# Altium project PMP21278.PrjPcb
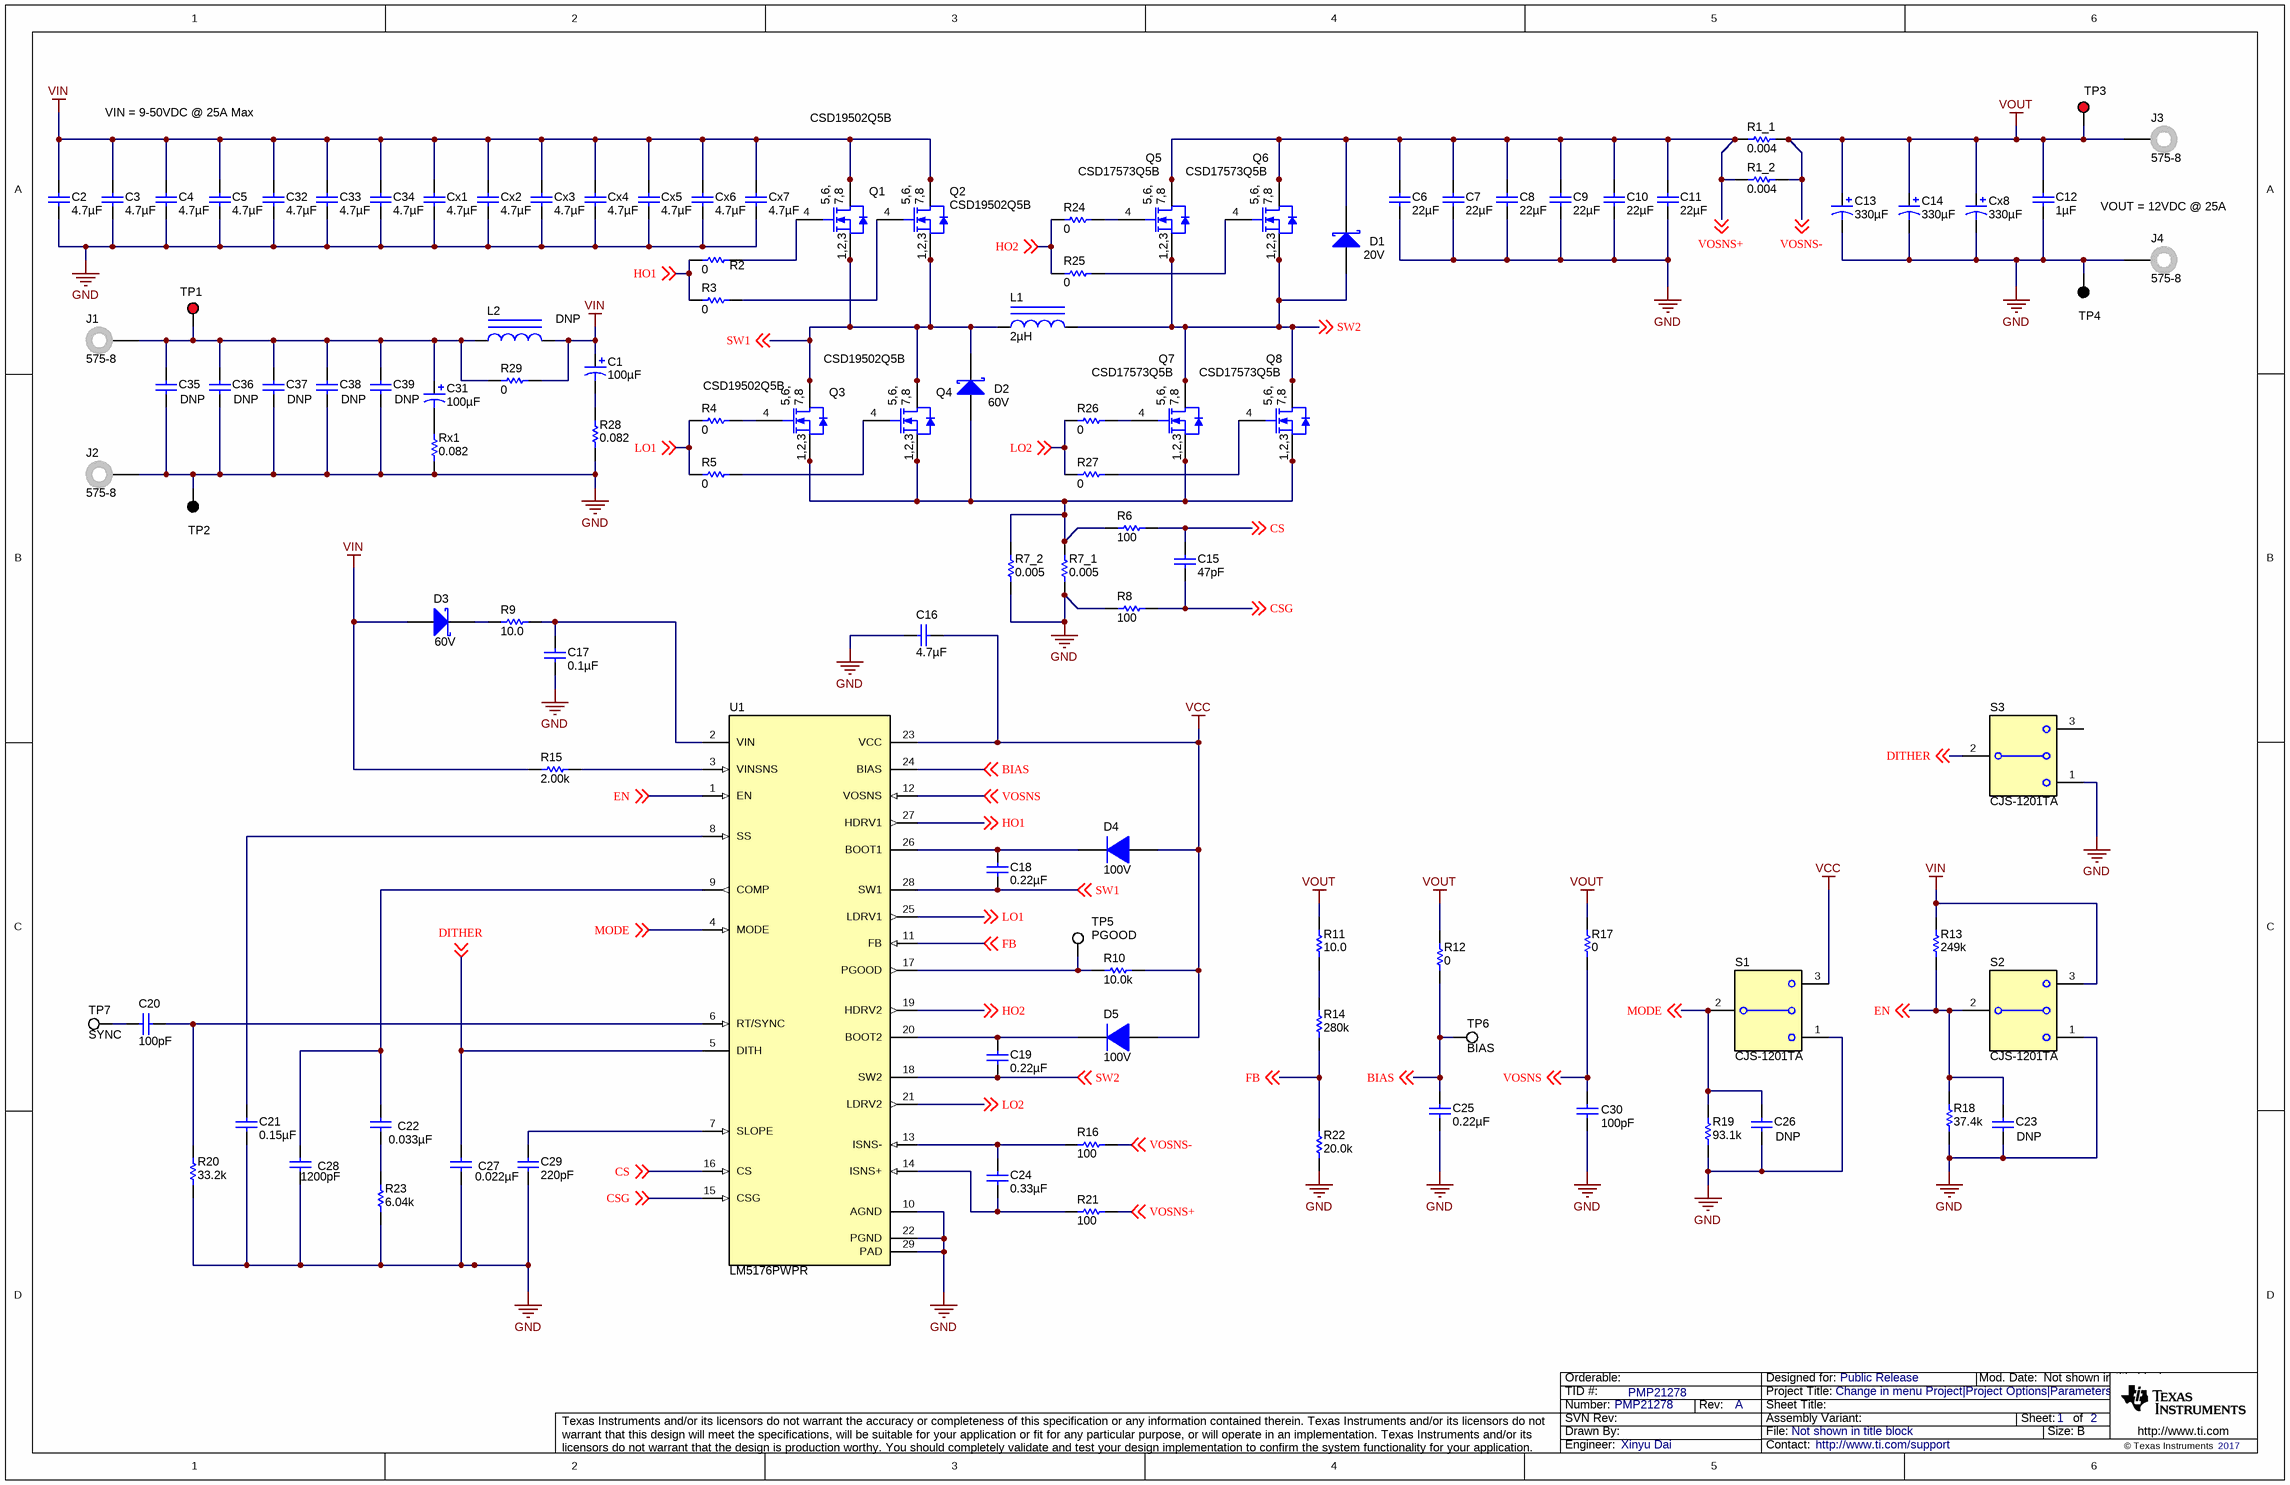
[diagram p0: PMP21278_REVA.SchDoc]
TID: PMP21278; TechSupport: http://www.ti.com/support; SCH_Rev: A; PRJ_Title: Change in menu Project|Project Options|Parameters; PRJ_Number: PMP21278; PRJ_Engineer: Xinyu Dai; PRJ_Customer: Public Release; PCB_Rev: A; PCB_Layout: Xinyu Dai; CopyrightYear: 2017
2 sheets, 125 parts. Net scope: global (net labels, ports and power ports of the same name join across sheets).
Board file: SV601348A.PcbDoc
Sheets:
  PMP21278_REVA.SchDoc
  SV601348_REVA_Hardware.SchDoc

## Sheet PMP21278_REVA.SchDoc
size 431 x 279 mm; Date: Not shown in title block; ApprovedBy: Not shown in title block; CheckedBy: Not shown in title block; Author: Not shown in title block; CompanyName: Not shown in title block; Engineer: Not shown in title block; Organization: Not shown in title block; Address1: Not shown in title block; Address2: Not shown in title block; Address3: Not shown in title block; Address4: Not shown in title block; DocumentNumber: 1; Revision: Use project parameter SCH_Rev; SheetNumber: 1; SheetTotal: 2; PageSetup: Record=PageOptions¦CenterHorizontal=True¦CenterVertical=True¦PrintScale=1.00¦XCorrection=1.00¦YCorrection=1.00¦PrintKind=0¦BorderSize=5000000¦LeftOffset=0¦BottomOffset=0¦Orientation=2¦PaperLength=1000¦PaperWidth=1000¦Scale=100¦PaperSource=15¦PrintQuality=600¦MediaType=1¦DitherType=10¦PaperKind=Letter¦PrintScaleMode=1

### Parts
C1  ValueDisplayed: 100µF  [CR_1000x1270]  (hidden comment: PCR1J101MCL1GS)
C2  ValueDisplayed: 4.7µF  [1210_270]  (hidden comment: GRM32ER71K475KE14L)
C3  ValueDisplayed: 4.7µF  [1210_270]  (hidden comment: GRM32ER71K475KE14L)
C4  ValueDisplayed: 4.7µF  [1210_270]  (hidden comment: GRM32ER71K475KE14L)
C5  ValueDisplayed: 4.7µF  [1210_270]  (hidden comment: GRM32ER71K475KE14L)
C6  ValueDisplayed: 22µF  [1210_270]  (hidden comment: GRM32ER71E226KE15L)
C7  ValueDisplayed: 22µF  [1210_270]  (hidden comment: GRM32ER71E226KE15L)
C8  ValueDisplayed: 22µF  [1210_270]  (hidden comment: GRM32ER71E226KE15L)
C9  ValueDisplayed: 22µF  [1210_270]  (hidden comment: GRM32ER71E226KE15L)
C10  ValueDisplayed: 22µF  [1210_270]  (hidden comment: GRM32ER71E226KE15L)
C11  ValueDisplayed: 22µF  [1210_270]  (hidden comment: GRM32ER71E226KE15L)
C12  ValueDisplayed: 1µF  [0805_HV]  (hidden comment: GRM219R71E105KA88D)
C13  ValueDisplayed: 330µF  [SM_RADIAL_10AMM]  (hidden comment: 16SVP330M)
C14  ValueDisplayed: 330µF  [SM_RADIAL_10AMM]  (hidden comment: 16SVP330M)
C15  ValueDisplayed: 47pF  [0603L]  (hidden comment: GRM1885C1H470JA01D)
C16  ValueDisplayed: 4.7µF  [0805_HV]  (hidden comment: GRM21BR71C475KA73L)
C17  ValueDisplayed: 0.1µF  [0603L]  (hidden comment: GRM188R72A104KA35D)
C18  ValueDisplayed: 0.22µF  [0603L]  (hidden comment: GRM188R71E224KA88D)
C19  ValueDisplayed: 0.22µF  [0603L]  (hidden comment: GRM188R71E224KA88D)
C20  ValueDisplayed: 100pF  [0603L]  (hidden comment: GRM1885C2A101JA01D)
C21  ValueDisplayed: 0.15µF  [0603]  (hidden comment: GRM188R71E154KA01D)
C22  ValueDisplayed: 0.033µF  [0603L]  (hidden comment: GRM188R71H333KA61D)
C23  DNP  [0603L]
C24  ValueDisplayed: 0.33µF  [0603L]  (hidden comment: GRM188R71C334KA01D)
C25  ValueDisplayed: 0.22µF  [0603]  (hidden comment: GRM188R71E224KA88D)
C26  DNP  [0603L]
C27  ValueDisplayed: 0.022µF  [0603L]  (hidden comment: C0603C223K5RACTU)
C28  ValueDisplayed: 1200pF  [0603]  (hidden comment: GRM188R71E122KA01D)
C29  ValueDisplayed: 220pF  [0603]  (hidden comment: GRM1885C1H221JA01D)
C30  ValueDisplayed: 100pF  [0603L]  (hidden comment: GRM1885C2A101JA01D)
C31  ValueDisplayed: 100µF  [CR_1000x1270]  (hidden comment: PCR1J101MCL1GS)
C32  ValueDisplayed: 4.7µF  [1210_270]  (hidden comment: GRM32ER71K475KE14L)
C33  ValueDisplayed: 4.7µF  [1210_270]  (hidden comment: GRM32ER71K475KE14L)
C34  ValueDisplayed: 4.7µF  [1210_270]  (hidden comment: GRM32ER71K475KE14L)
C35  DNP  [1210_270]
C36  DNP  [1210_270]
C37  DNP  [1210_270]
C38  DNP  [1210_270]
C39  DNP  [1210_270]
Cx1  ValueDisplayed: 4.7µF  [1210_270]  (hidden comment: GRM32ER71K475KE14L)
Cx2  ValueDisplayed: 4.7µF  [1210_270]  (hidden comment: GRM32ER71K475KE14L)
Cx3  ValueDisplayed: 4.7µF  [1210_270]  (hidden comment: GRM32ER71K475KE14L)
Cx4  ValueDisplayed: 4.7µF  [1210_270]  (hidden comment: GRM32ER71K475KE14L)
Cx5  ValueDisplayed: 4.7µF  [1210_270]  (hidden comment: GRM32ER71K475KE14L)
Cx6  ValueDisplayed: 4.7µF  [1210_270]  (hidden comment: GRM32ER71K475KE14L)
Cx7  ValueDisplayed: 4.7µF  [1210_270]  (hidden comment: GRM32ER71K475KE14L)
Cx8  ValueDisplayed: 330µF  [SM_RADIAL_10AMM]  (hidden comment: 16SVP330M)
D1  20V  [SMA]
D2  60V  [SMA]
D3  60V  [SOD-323F]
D4  100V  [sod-323]
D5  100V  [sod-323]
J1  575-8  [Keystone575-8]
J2  575-8  [Keystone575-8]
J3  575-8  [Keystone575-8]
J4  575-8  [Keystone575-8]
L1  ValueDisplayed: 2µH  [XAL1580]  (hidden comment: XAL1580-202MEB)
L2  DNP  [XAL1010]
Q1  CSD19502Q5B  [DNK0008A]
Q2  CSD19502Q5B  [DNK0008A]
Q3  CSD19502Q5B  [DNK0008A]
Q4  CSD19502Q5B  [DNK0008A]
Q5  CSD17573Q5B  [DNK0008A]
Q6  CSD17573Q5B  [DNK0008A]
Q7  CSD17573Q5B  [DNK0008A]
Q8  CSD17573Q5B  [DNK0008A]
R1_1  ValueDisplayed: 0.004  [2512_WIDE]  (hidden comment: KRL6432E-M-R004-F-T1)
R1_2  ValueDisplayed: 0.004  [2512_WIDE]  (hidden comment: KRL6432E-M-R004-F-T1)
R2  value 0  [0603L]  (hidden comment: RC0603JR-070RL)
R3  value 0  [0603L]  (hidden comment: RC0603JR-070RL)
R4  value 0  [0603L]  (hidden comment: RC0603JR-070RL)
R5  value 0  [0603L]  (hidden comment: RC0603JR-070RL)
R6  value 100  [0603_HV]  (hidden comment: RC0603FR-07100RL)
R7_1  ValueDisplayed: 0.005  [2512_WIDE]  (hidden comment: FCSL64R005FER)
R7_2  ValueDisplayed: 0.005  [2512_WIDE]  (hidden comment: FCSL64R005FER)
R8  value 100  [0603_HV]  (hidden comment: RC0603FR-07100RL)
R9  value 10.0  [0603L]  (hidden comment: RC0603FR-0710RL)
R10  value 10.0k  [0603L]  (hidden comment: RC0603FR-0710KL)
R11  value 10.0  [0603L]  (hidden comment: RC0603FR-0710RL)
R12  value 0  [0603L]  (hidden comment: RC0603JR-070RL)
R13  value 249k  [0603L]  (hidden comment: RC0603FR-07249KL)
R14  value 280k  [0603L]  (hidden comment: RC0603FR-07280KL)
R15  ValueDisplayed: 2.00k  [0603]  (hidden comment: CRCW06032K00FKEA)
R16  100  [0603L]
R17  value 0  [0603L]  (hidden comment: RC0603JR-070RL)
R18  ValueDisplayed: 37.4k  [0603]  (hidden comment: CRCW060337K4FKEA)
R19  ValueDisplayed: 93.1k  [0603L]  (hidden comment: RC0603FR-0793K1L)
R20  ValueDisplayed: 33.2k  [0603L]  (hidden comment: CRCW060333K2FKEA)
R21  100  [0603L]
R22  value 20.0k  [0603L]  (hidden comment: RC0603FR-0720KL)
R23  ValueDisplayed: 6.04k  [0603]  (hidden comment: CRCW06036K04FKEA)
R24  value 0  [0603L]  (hidden comment: RC0603JR-070RL)
R25  value 0  [0603L]  (hidden comment: RC0603JR-070RL)
R26  value 0  [0603L]  (hidden comment: RC0603JR-070RL)
R27  value 0  [0603L]  (hidden comment: RC0603JR-070RL)
R28  ValueDisplayed: 0.082  [2512]  (hidden comment: RLP73N3AR082FTDF)
R29  ValueDisplayed: 0  [2512_WIDE_VISHAY]  (hidden comment: RCL12250000Z0EG)
Rx1  ValueDisplayed: 0.082  [2512]  (hidden comment: RLP73N3AR082FTDF)
S1  CJS-1201TA  [SW_CJS_1201A]
S2  CJS-1201TA  [SW_CJS_1201A]
S3  CJS-1201TA  [SW_CJS_1201A]
TP1  5005  [Keystone5005]  (value not drawn)
TP2  5006  [Keystone5006]  (value not drawn)
TP3  5005  [Keystone5005]  (value not drawn)
TP4  5006  [Keystone5006]  (value not drawn)
TP5  PGOOD  [Keystone5007]
TP6  BIAS  [Keystone5007]
TP7  SYNC  [Keystone5007]
U1  LM5176PWPR  [PWP0028C_N]

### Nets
GND: C2.2 C3.2 C4.2 C5.2 C6.2 C7.2 C8.2 C9.2 C10.2 C11.2 C12.2 C13.2(-) C14.2(-) C16.1 C17.2 C21.2 C23.2 C25.2 C26.2 C27.2 C28.2 C29.2 C30.2 C32.2 C33.2 C34.2 C35.2 C36.2 C37.2 C38.2 C39.2 Cx1.2 Cx2.2 Cx3.2 Cx4.2 Cx5.2 Cx6.2 Cx7.2 Cx8.2(-) J2.1 J4.1 R7_1.1 R7_2.1 R8.2 R18.1 R19.1 R20.1 R22.1 R23.1 R28.1 Rx1.1 S1.1 S2.1 S3.1 TP2.1 TP4.1 U1.10(AGND) U1.22(PGND) U1.29(PAD)
VCC: C16.2 D4.2(A) D5.2(A) R10.2 S1.3 U1.23(VCC)
VIN: C1.1(+) C2.1 C3.1 C4.1 C5.1 C32.1 C33.1 C34.1 Cx1.1 Cx2.1 Cx3.1 Cx4.1 Cx5.1 Cx6.1 Cx7.1 D3.2(A) L2.2 Q1.5(D) Q1.6(D) Q1.7(D) Q1.8(D) Q1.9(D) Q2.5(D) Q2.6(D) Q2.7(D) Q2.8(D) Q2.9(D) R13.2 R15.2 R29.2 S2.3
VOUT: C12.1 C13.1(+) C14.1(+) Cx8.1(+) J3.1 R1_1.2 R1_2.2 R11.1 R12.1 R16.2 R17.1 TP3.1 ; off-sheet VOSNS-  [also labelled VOSNS-]
BIAS: C25.1 R12.2 TP6.1 U1.24(BIAS) ; off-sheet BIAS
CS: C15.1 R6.1 U1.16(CS) ; off-sheet CS
CSG: C15.2 R8.1 U1.15(CSG) ; off-sheet CSG
DITHER: C27.1 S3.2(COM) U1.5(DITH) ; off-sheet DITHER
EN: C23.1 R13.1 R18.2 S2.2(COM) U1.1(EN) ; off-sheet EN
FB: R14.1 R22.2 U1.11(FB) ; off-sheet FB
HO1: R2.2 R3.2 U1.27(HDRV1) ; off-sheet HO1
HO2: R24.2 R25.2 U1.19(HDRV2) ; off-sheet HO2
LO1: R4.2 R5.2 U1.25(LDRV1) ; off-sheet LO1
LO2: R26.2 R27.2 U1.21(LDRV2) ; off-sheet LO2
MODE: C26.1 R19.2 S1.2(COM) U1.4(MODE) ; off-sheet MODE
SW1: C18.1 D2.1(K) L1.1 Q1.1(S) Q1.2(S) Q1.3(S) Q2.1(S) Q2.2(S) Q2.3(S) Q3.5(D) Q3.6(D) Q3.7(D) Q3.8(D) Q3.9(D) Q4.5(D) Q4.6(D) Q4.7(D) Q4.8(D) Q4.9(D) U1.28(SW1) ; off-sheet SW1
SW2: C19.2 D1.2(A) L1.2 Q5.1(S) Q5.2(S) Q5.3(S) Q6.1(S) Q6.2(S) Q6.3(S) Q7.5(D) Q7.6(D) Q7.7(D) Q7.8(D) Q7.9(D) Q8.5(D) Q8.6(D) Q8.7(D) Q8.8(D) Q8.9(D) U1.18(SW2) ; off-sheet SW2
VOSNS: C30.1 R17.2 U1.12(VOSNS) ; off-sheet VOSNS
VOSNS+: C6.1 C7.1 C8.1 C9.1 C10.1 C11.1 D1.1(K) Q5.5(D) Q5.6(D) Q5.7(D) Q5.8(D) Q5.9(D) Q6.5(D) Q6.6(D) Q6.7(D) Q6.8(D) Q6.9(D) R1_1.1 R1_2.1 R21.2 ; off-sheet VOSNS+
NetC1_2: C1.2(-) R28.2
NetC17_1: C17.1 R9.1 U1.2(VIN)
NetC18_2: C18.2 D4.1(K) U1.26(BOOT1)
NetC19_1: C19.1 D5.1(K) U1.20(BOOT2)
NetC20_1: C20.1 TP7.1
NetC20_2: C20.2 R20.2 U1.6(RT/SYNC)
NetC21_1: C21.1 U1.8(SS)
NetC22_1: C22.1 C28.1 U1.9(COMP)
NetC22_2: C22.2 R23.2
NetC24_1: C24.1 R16.1 U1.13(ISNS-)
NetC24_2: C24.2 R21.1 U1.14(ISNS+)
NetC29_1: C29.1 U1.7(SLOPE)
NetC31_1: C31.1(+) C35.1 C36.1 C37.1 C38.1 C39.1 J1.1 L2.1 R29.1 TP1.1
NetC31_2: C31.2(-) Rx1.2
NetD2_2: D2.2(A) Q3.1(S) Q3.2(S) Q3.3(S) Q4.1(S) Q4.2(S) Q4.3(S) Q7.1(S) Q7.2(S) Q7.3(S) Q8.1(S) Q8.2(S) Q8.3(S) R6.2 R7_1.2 R7_2.2
NetD3_1: D3.1(K) R9.2
NetQ1_4: Q1.4(G) R2.1
NetQ2_4: Q2.4(G) R3.1
NetQ3_4: Q3.4(G) R4.1
NetQ4_4: Q4.4(G) R5.1
NetQ5_4: Q5.4(G) R24.1
NetQ6_4: Q6.4(G) R25.1
NetQ7_4: Q7.4(G) R26.1
NetQ8_4: Q8.4(G) R27.1
NetR10_1: R10.1 TP5.1 U1.17(PGOOD)
NetR11_2: R11.2 R14.2
NetR15_1: R15.1 U1.3(VINSNS)

Not connected (* = marked no-connect by the designer): S3 3

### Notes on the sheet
- VIN = 9-50VDC @ 25A Max
- VOUT = 12VDC @ 25A

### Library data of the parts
C1 C31 = PCR1J101MCL1GS: CAP, Aluminum Polymer, 100 µF, 63 V, +/- 20%, 0.024 ohm, SMD, 2-Leads, Dia 10.5mm, Pin Spacing 8mm SMD; Manufacturer: Nichicon; Polarized: Y; CompType: Capacitor; Value: 100uF; U/M: EA; Cap_F: 0.0001; Tolerance_%: 20; VDC_V: 63; Value2: 63V; ESR_ohm: 0.024; IRMS_A: 3; TaMin_C: -55; TaMax_C: 125; Cap_Case: 10x12.7mm; AEC Category: Q200; AEC Qualified: N
C2-C5 C32-C34 Cx1-Cx7 = GRM32ER71K475KE14L: CAP, CERM, 4.7 µF, 80 V, +/- 10%, X7R, 1210; Manufacturer: MuRata; CompType: Capacitor; Value: 4.7uF; U/M: EA; Tolerance_%: 10; VDC_V: 80; Polarized: N; Cap_F: 0.0000047; Value1: Unknown; Value2: 80V; TaMin_C: -55; TaMax_C: 125; Cap_Case: 1210; SizeArea_mm2: 8; SizeAreaWB_mm2: 14.7; SizeX_mm: 3.2; SizeY_mm: 2.5; SizeZ_mm: 2.7; AEC Category: Q200
C6-C11 = GRM32ER71E226KE15L: CAP, CERM, 22 µF, 25 V, +/- 10%, X7R, 1210; Manufacturer: MuRata; CompType: Capacitor; Value: 22uF; U/M: EA; Tolerance_%: 10; VDC_V: 25; Polarized: N; Cap_F: 0.000022; Value1: Unknown; Value2: 25V; TaMin_C: -55; TaMax_C: 125; Cap_Case: 1210; SizeArea_mm2: 8; SizeAreaWB_mm2: 14.7; SizeX_mm: 3.2; SizeY_mm: 2.5; SizeZ_mm: 2.7; AEC Category: Q200
C12 = GRM219R71E105KA88D: CAP, CERM, 1 µF, 25 V, +/- 10%, X7R, 0805; Manufacturer: MuRata; Polarized: N; CompType: Capacitor; Value: 1uF; U/M: EA; Cap_F: 0.000001; Tolerance_%: 10; Value1: Unknown; VDC_V: 25; Value2: 25V; TaMin_C: -55; TaMax_C: 125; Cap_Case: 0805
C13 C14 Cx8 = 16SVP330M: CAP, OS-CON, 330 µF, 16 V, +/- 20%, 0.016 ohm, 10x10.3 SMD; Manufacturer: Sanyo; CompType: Capacitor; Value: 330uF; U/M: EA; Tolerance_%: 20; VDC_V: 16; ESR_ohm: 0.016; Polarized: Y; Cap_F: 0.00033; Value2: 16V; IRMS_A: 4.72; TaMin_C: -55; TaMax_C: 105; Cap_Case: 10.3x10.3x12.6
C15 C23 C26 = GRM1885C1H470JA01D: CAP, CERM, 47pF, 50V, +/-5%, C0G/NP0, 0603; Manufacturer: MuRata; Polarized: N; CompType: Capacitor; U/M: EA; Cap_F: 0.000000000047; Tolerance_%: 5; Value1: Unknown; VDC_V: 50; TaMin_C: -55; TaMax_C: 125; Cap_Case: 0603
C16 = GRM21BR71C475KA73L: CAP, CERM, 4.7 µF, 16 V, +/- 10%, X7R, 0805; Manufacturer: MuRata; Polarized: N; CompType: Capacitor; Value: 4.7uF; U/M: EA; Cap_F: 0.0000047; Tolerance_%: 10; ESR_ohm: 0.006; Value1: 0.006 ohm; VDC_V: 16; Value2: 16V; TaMin_C: -55; TaMax_C: 125; Cap_Case: 0805
C17 = GRM188R72A104KA35D: CAP, CERM, 0.1uF, 100V, +/-10%, X7R, 0603; Manufacturer: MuRata; Polarized: N; CompType: Capacitor; U/M: EA; Cap_F: 0.0000001; Tolerance_%: 10; Value1: Unknown; VDC_V: 100; TaMin_C: -55; TaMax_C: 125; Cap_Case: 0603
C18 C19 = GRM188R71E224KA88D: CAP, CERM, 0.22 µF, 25 V, +/- 10%, X7R, 0603; Manufacturer: MuRata; Polarized: N; CompType: Capacitor; Value: 0.22uF; U/M: EA; Cap_F: 0.00000022; Tolerance_%: 10; Value1: Unknown; VDC_V: 25; Value2: 25V; TaMin_C: -55; TaMax_C: 125; Cap_Case: 0603
C20 C30 = GRM1885C2A101JA01D: CAP, CERM, 100pF, 100V, +/-5%, C0G/NP0, 0603; Manufacturer: MuRata; Polarized: N; CompType: Capacitor; U/M: EA; Cap_F: 0.0000000001; Tolerance_%: 5; Value1: Unknown; VDC_V: 100; TaMin_C: -55; TaMax_C: 125; Cap_Case: 0603
C21 = GRM188R71E154KA01D: CAP, CERM, 0.15 µF, 25 V,+/- 10%, X7R, 0603; Manufacturer: MuRata; Polarized: N; CompType: Capacitor; Value: 0.15uF; U/M: EA; Cap_F: 0.00000015; Tolerance_%: 10; Value1: Unknown; VDC_V: 25; Value2: 25V; TaMin_C: -55; TaMax_C: 125; SizeArea_mm2: 1.28; SizeAreaWB_mm2: 4.68; SizeX_mm: 1.6; SizeY_mm: 0.8; SizeZ_mm: 1; AEC Category: Q200; Green_Lifecycle: Active; Green_REACh: Passed
C22 = GRM188R71H333KA61D: CAP, CERM, 0.033 µF, 50 V, +/- 10%, X7R, 0603; Manufacturer: MuRata; Polarized: N; CompType: Capacitor; Value: 0.033uF; U/M: EA; Cap_F: 0.000000033; Tolerance_%: 10; Value1: Unknown; VDC_V: 50; Value2: 50V; TaMin_C: -55; TaMax_C: 125; Cap_Case: 0603; SizeArea_mm2: 1.28; SizeAreaWB_mm2: 4.68; SizeX_mm: 1.6; SizeY_mm: 0.8; SizeZ_mm: 1; AEC Category: Q200
C24 = GRM188R71C334KA01D: CAP, CERM, 0.33 µF, 16 V, +/- 10%, X7R, 0603; Manufacturer: MuRata; Polarized: N; CompType: Capacitor; Value: 0.33uF; U/M: EA; Cap_F: 0.00000033; Tolerance_%: 10; Value1: Unknown; VDC_V: 16; Value2: 16V; TaMin_C: -55; TaMax_C: 125; Cap_Case: 0603
C25 = GRM188R71E224KA88D: CAP, CERM, 0.22 µF, 25 V, +/- 10%, X7R, 0603; Manufacturer: MuRata; Polarized: N; CompType: Capacitor; Value: 0.22uF; U/M: EA; Cap_F: 0.00000022; Tolerance_%: 10; Value1: Unknown; VDC_V: 25; Value2: 25V; TaMin_C: -55; TaMax_C: 125
C27 = C0603C223K5RACTU: CAP, CERM, 0.022uF, 50V, +/-10%, X7R, 0603; Manufacturer: Kemet; Polarized: N; CompType: Capacitor; U/M: EA; Cap_F: 0.000000022; Tolerance_%: 10; Value1: Unknown; VDC_V: 50; TaMin_C: -55; TaMax_C: 125; Cap_Case: 0603
C28 = GRM188R71E122KA01D: CAP, CERM, 1200 pF, 25 V,+/- 10%, X7R, 0603; Manufacturer: MuRata; Polarized: N; CompType: Capacitor; Value: 1200pF; U/M: EA; Cap_F: 0.0000000012; Tolerance_%: 10; Value1: Unknown; VDC_V: 25; Value2: 25V; TaMin_C: -55; TaMax_C: 125; SizeArea_mm2: 1.28; SizeAreaWB_mm2: 4.68; SizeX_mm: 1.6; SizeY_mm: 0.8; SizeZ_mm: 1; AEC Category: Q200
C29 = GRM1885C1H221JA01D: CAP, CERM, 220 pF, 50 V,+/- 5%, C0G/NP0, 0603; Manufacturer: MuRata; Polarized: N; CompType: Capacitor; Value: 220pF; U/M: EA; Cap_F: 0.00000000022; Tolerance_%: 5; Value1: Unknown; VDC_V: 50; Value2: 50V; TaMin_C: -55; TaMax_C: 125; SizeArea_mm2: 1.28; SizeAreaWB_mm2: 4.68; SizeX_mm: 1.6; SizeY_mm: 0.8; SizeZ_mm: 1; AEC Category: Q200; Green_Lifecycle: Active; Green_REACh: Passed
C35-C39 = GRM32ER71K475KE14L: CAP, CERM, 4.7 µF, 80 V, +/- 10%, X7R, 1210; Manufacturer: MuRata; CompType: Capacitor; Value: 4.7uF; U/M: EA; Tolerance_%: 10; VDC_V: 80; Polarized: N; ValueDisplayed: 4.7µF; Cap_F: 0.0000047; Value1: Unknown; Value2: 80V; TaMin_C: -55; TaMax_C: 125; Cap_Case: 1210; SizeArea_mm2: 8; SizeAreaWB_mm2: 14.7; SizeX_mm: 3.2; SizeY_mm: 2.5; SizeZ_mm: 2.7; AEC Category: Q200
D1 = RSX501L-20TE25: Diode, Schottky, 20 V, 5 A, SMA; Manufacturer: Rohm; U/M: EA; Vf_V: 0.39; Value1: 5A; Value2: 0.39V; Io_A: 5; Vr_V: 20; TJmax_C: 125
D2 = RB050L-60TE25: Diode, Schottky, 60 V, 3 A, SMA; Manufacturer: Rohm; U/M: EA; Vf_V: 0.56; Value1: 3A; Value2: 0.56V; Io_A: 3; Vr_V: 60; TJmax_C: 150
D3 = PMEG6010CEJ,115: Diode, Schottky, 60 V, 1 A, SOD-323F; Manufacturer: NXP Semiconductor; U/M: EA; Vf_V: 0.66; Value1: 1A; Value2: 0.66V; Io_A: 1; Vr_V: 60; TJmax_C: 150
D4 D5 = BAS316,115: Diode, Ultrafast, 100V, 0.25A, SOD-323; Manufacturer: NXP Semiconductor; U/M: EA; Vr_V: 100; Io_A: 0.25; Vf_V: 1.4; Value2: 1.4V; TJmax_C: 150
J1-J4 = 575-8: Standard Banana Jack, Uninsulated, 8.9mm; Manufacturer: Keystone; CompType: Connector
L1 = XAL1580-202MEB: Inductor, Shielded, Composite, 2 µH, 39.9 A, 0.001909 ohm, SMD; Manufacturer: Coilcraft; Value: 2uH; Ind_H: 2.0E-6; Imax_A: 39.9; Irms: 39.9A @ 40C rise; Isat: 51A @ 0.7% inductance drop; Value2: 39.9A; SizeAreaWB_mm2: 313.04; SizeArea_mm2: 246.24; SizeX_mm: 15.2; SizeY_mm: 16.2; SizeZ_mm: 8; AEC Category: Q200; Green_Lifecycle: Not Set; Green_REACh: Incomplete
L2 = XAL1010-222MEB: Inductor, Shielded, Composite, 2.2 µH, 32 A, 0.00255 ohm, SMD; Manufacturer: Coilcraft; Value: 2.2uH; ValueDisplayed: 2.2µH; Ind_H: 2.2E-6; Imax_A: 32; Irms: 32A @ 40C rise; Isat: 34A @ 30% inductance drop; Value2: 32A; SizeAreaWB_mm2: 159.6; SizeArea_mm2: 113; SizeX_mm: 11.3; SizeY_mm: 10; AEC Category: Q200
Q1-Q4 = CMP-0000915-1: MOSFET, N-CH, 80 V, 100 A, DNK0008A (VSON-CLIP-8); Alternate Manufacturer: None; Manufacturer: Texas Instruments; SizeZ_mm: 1; ChType: N; Value2: 48 nC; VdsMax_V: 80V; SizeX_mm: 6; SizeY_mm: 5; Vgs_V: 20V; Value: 80V; SizeArea_mm2: 30; AEC Category: Q101; IdsMax_A: 100A; SizeAreaWB_mm2: 56; U/M: EA; QgTyp_nC: 48
Q5-Q8 = CSD17573Q5B: MOSFET, N-CH, 30 V, 100 A, DNK0008A (VSON-CLIP-8); Manufacturer: Texas Instruments; Alternate Manufacturer: None; U/M: EA; ChType: N; Value: 30V; VdsMax_V: 30; Value1: 0.00145 ohm; Rdson45_ohm: 0.00145; Value2: 49 nC; QgTyp_nC: 49; Vgs_V: 20; IdsMax_A: 100; SizeAreaWB_mm2: 56; SizeX_mm: 6; SizeY_mm: 5; SizeZ_mm: 1; AEC Category: Q101
R1_1 R1_2 = KRL6432E-M-R004-F-T1: RES, 0.004, 1%, 3 W, 2512 WIDE; Manufacturer: Susumu Co Ltd; CompType: Resistor; U/M: EA; Value: 0.004; Power_W: 3; Tolerance_%: 1; TempCo: 50 ppm/C; Value_Code: 4L000; Value2: 3W; SizeArea_mm2: 20.16; SizeAreaWB_mm2: 43.16; SizeX_mm: 3.2; SizeY_mm: 6.3; SizeZ_mm: 0.7; AEC Category: Q200
R2-R5 R12 R17 R24-R27 = RC0603JR-070RL: RES, 0 ohm, 5%, 0.1W, 0603; Manufacturer: Yageo America; CompType: Resistor; Value_Code: 0000; Tolerance_%: 5; Power_W: 0.1; VDC_V: 50; TempCo: 200 ppm/C; EIA_Code: E24; U/M: EA
R6 R8 R16 R21 = RC0603FR-07100RL: RES, 100 ohm, 1%, 0.1W, 0603; Manufacturer: Yageo America; CompType: Resistor; Value_Code: 100R; Tolerance_%: 1; Power_W: 0.1; VDC_V: 150; TempCo: 200 ppm/C; EIA_Code: E96; U/M: EA
R7_1 = FCSL64R005FER: RES, 0.005, 1%, 2 W, 2512 WIDE; Manufacturer: Ohmite; CompType: Resistor; Value: 0.005; Tolerance_%: 1; Power_W: 2; TempCo: 75 ppm/C; U/M: EA; Value_Code: 5L000; Value2: 2W; EIA_Code: E96; SizeArea_mm2: 20.16; SizeAreaWB_mm2: 43.16; SizeX_mm: 3.2; SizeY_mm: 6.3; SizeZ_mm: 0.7; AEC Category: Q200
R7_2 = FCSL64R005FER: RES, 0.005, 1%, 2 W, 2512 WIDE; Manufacturer: Ohmite; CompType: Resistor; Value: 0.005; Value_Code: 5L000; Tolerance_%: 1; Power_W: 2; Value2: 2W; TempCo: 75 ppm/C; SizeArea_mm2: 20.16; SizeAreaWB_mm2: 43.16; SizeX_mm: 3.2; SizeY_mm: 6.3; SizeZ_mm: 0.7; EIA_Code: E96; U/M: EA; AEC Category: Q200
R9 R11 = RC0603FR-0710RL: RES, 10.0 ohm, 1%, 0.1W, 0603; Manufacturer: Yageo America; CompType: Resistor; Res_ohm: 10; Value_Code: 10R0; Tolerance_%: 1; Power_W: 0.1; VDC_V: 150; TempCo: 200 ppm/C; EIA_Code: E96; U/M: EA
R10 = RC0603FR-0710KL: RES, 10.0k ohm, 1%, 0.1W, 0603; Manufacturer: Yageo America; CompType: Resistor; Res_ohm: 10000; Value_Code: 10k0; Tolerance_%: 1; Power_W: 0.1; VDC_V: 150; TempCo: 200 ppm/C; EIA_Code: E96; U/M: EA
R13 = RC0603FR-07249KL: RES, 249k ohm, 1%, 0.1W, 0603; Manufacturer: Yageo America; CompType: Resistor; Res_ohm: 249000; Tolerance_%: 1; Power_W: 0.1; VDC_V: 150; TempCo: 200 ppm/C; EIA_Code: E96; U/M: EA
R14 = RC0603FR-07280KL: RES, 280k ohm, 1%, 0.1W, 0603; Manufacturer: Yageo America; CompType: Resistor; Res_ohm: 280000; Tolerance_%: 1; Power_W: 0.1; VDC_V: 150; TempCo: 200 ppm/C; EIA_Code: E96; U/M: EA
R15 = CRCW06032K00FKEA: RES, 2.00 k, 1%, 0.1 W, 0603; Manufacturer: Vishay-Dale; CompType: Resistor; Value: 2.00k; Res_ohm: 2000; Value_Code: 2k00; Tolerance_%: 1; Power_W: 0.1; Value2: 0.1W; VDC_V: 75; TempCo: 100 ppm/C; EIA_Code: E96; U/M: EA; SizeArea_mm2: 1.28; SizeX_mm: 1.6; SizeY_mm: 0.8; AEC Category: Q200
R18 = CRCW060337K4FKEA: RES, 37.4 k, 1%, 0.1 W, 0603; Manufacturer: Vishay-Dale; CompType: Resistor; Value: 37.4k; Res_ohm: 37400; Value_Code: 37k4; Tolerance_%: 1; Power_W: 0.1; Value2: 0.1W; VDC_V: 75; TempCo: 100 ppm/C; EIA_Code: E96; U/M: EA; SizeArea_mm2: 1.28; SizeX_mm: 1.6; SizeY_mm: 0.8; AEC Category: Q200; Green_Lifecycle: Active; Green_REACh: Passed
R19 = RC0603FR-0793K1L: RES, 93.1 k, 1%, 0.1 W, 0603; Manufacturer: Yageo America; CompType: Resistor; Value: 93.1k; Res_ohm: 93100; Value_Code: 93k1; Tolerance_%: 1; Power_W: 0.1; Value2: 0.1W; VDC_V: 150; TempCo: 200 ppm/C; EIA_Code: E96; U/M: EA
R20 = CRCW060333K2FKEA: RES, 33.2 k, 1%, 0.1 W, 0603; Manufacturer: Vishay-Dale; CompType: Resistor; Value: 33.2k; Res_ohm: 33200; Value_Code: 33k2; Tolerance_%: 1; Power_W: 0.1; Value2: 0.1W; VDC_V: 75; TempCo: 100 ppm/C; EIA_Code: E96; U/M: EA; SizeArea_mm2: 1.28; SizeX_mm: 1.6; SizeY_mm: 0.8; AEC Category: Q200
R22 = RC0603FR-0720KL: RES, 20.0k ohm, 1%, 0.1W, 0603; Manufacturer: Yageo America; CompType: Resistor; Res_ohm: 20000; Value_Code: 20k0; Tolerance_%: 1; Power_W: 0.1; VDC_V: 150; TempCo: 200 ppm/C; EIA_Code: E96; U/M: EA
R23 = CRCW06036K04FKEA: RES, 6.04 k, 1%, 0.1 W, 0603; Manufacturer: Vishay-Dale; CompType: Resistor; Value: 6.04k; Res_ohm: 6040; Value_Code: 6k04; Tolerance_%: 1; Power_W: 0.1; Value2: 0.1W; VDC_V: 75; TempCo: 100 ppm/C; EIA_Code: E96; U/M: EA; SizeArea_mm2: 1.28; SizeX_mm: 1.6; SizeY_mm: 0.8; AEC Category: Q200; Green_Lifecycle: Active; Green_REACh: Passed
R28 Rx1 = CMP-0078954-1: RES, 0.082, 1%, 2 W, AEC-Q200 Grade 0, 2512; Manufacturer: TE Connectivity; Value_Code: R082; SizeArea_mm2: 20.16; AEC Qualified: Y; AEC Category: Q200; Value: 0.082; SizeZ_mm: 0.71; TempCo: 300 ppm/C; AEC Grade: 0; SizeY_mm: 3.2; Power_W: 2W; CompType: Resistor; SizeX_mm: 6.3
R29 = RCL12250000Z0EG: RES, 0, 5%, 2 W, 2512 WIDE; Manufacturer: Vishay Draloric; CompType: Resistor; Value: 0; Value_Code: 0000; Tolerance_%: 5; Power_W: 2; Value2: 2W; TempCo: ppm/C; EIA_Code: E24; U/M: EA; AEC Category: Q200
S1-S3 = CJS-1201TA: Slide SW, SPDT 0.1A 50VDC; Manufacturer: Copal Electronics; SymbolCreator: a0799628; VDC_V: 50; SwitchFunction: On-Off-On; PositionCount: 1; CurrentRating_mA: 100; CompType: Switch
TP1 TP3 = 5005: Test Point, Compact, Red, TH; Manufacturer: Keystone; CompType: Test Point Loop; U/M: EA
TP2 TP4 = 5006: Test Point, Compact, Black, TH; Manufacturer: Keystone; CompType: Test Point Loop; U/M: EA
TP5-TP7 = 5007: Test Point, Compact, White, TH; Manufacturer: Keystone; CompType: Test Point Loop; U/M: EA
U1 = LM5176PWPR: 55 V Wide VIN Synchronous 4-Switch Buck-Boost Controller, PWP0028C (TSSOP-28); Alternate PartNumber: LM5176PWPT; Manufacturer: Texas Instruments; SymbolCreator: a0411947; SizeArea_mm2: 62.08; SizeAreaWB_mm2: 98.28; SizeX_mm: 6.4; SizeY_mm: 9.7; SizeZ_mm: 1.2; CompType: IC; U/M: EA

## Sheet SV601348_REVA_Hardware.SchDoc
size 431 x 279 mm; Date: Not shown in title block; ApprovedBy: Not shown in title block; CheckedBy: Not shown in title block; Author: Not shown in title block; CompanyName: Not shown in title block; Engineer: Not shown in title block; Organization: Not shown in title block; Address1: Not shown in title block; Address2: Not shown in title block; Address3: Not shown in title block; Address4: Not shown in title block; DocumentNumber: 2; Revision: Use project parameter SCH_Rev; SheetNumber: 2; SheetTotal: 2; PageSetup: Record=PageOptions¦CenterHorizontal=True¦CenterVertical=True¦PrintScale=1.00¦XCorrection=1.00¦YCorrection=1.00¦PrintKind=0¦BorderSize=5000000¦LeftOffset=0¦BottomOffset=0¦Orientation=2¦PaperLength=1000¦PaperWidth=1000¦Scale=100¦PaperSource=15¦PrintQuality=600¦MediaType=1¦DitherType=10¦PaperKind=Letter¦PrintScaleMode=1
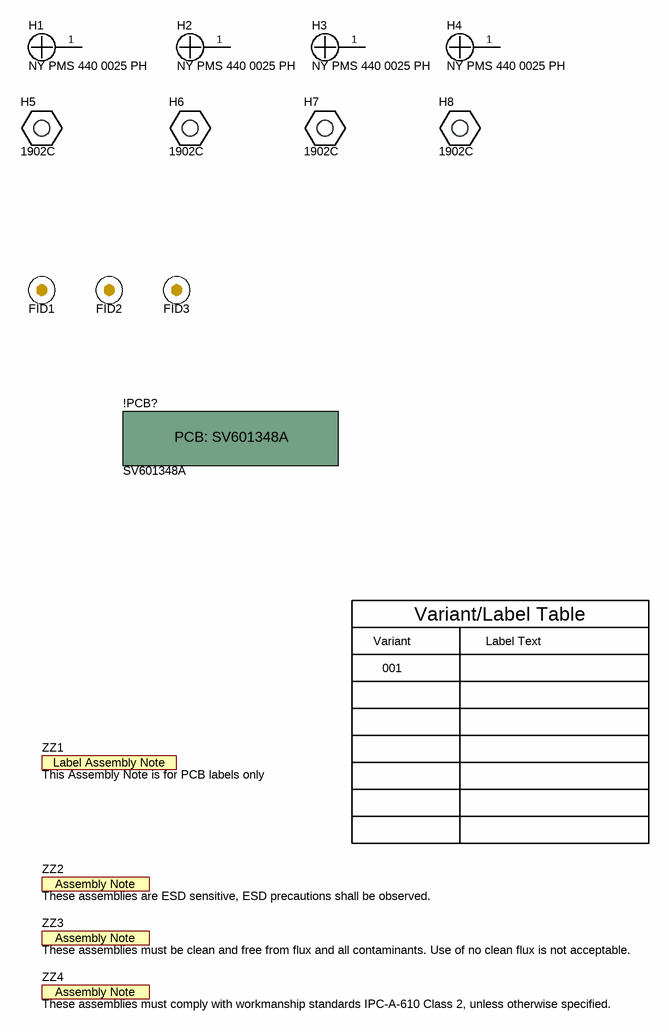
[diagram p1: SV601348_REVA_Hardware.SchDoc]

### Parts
!PCB?  SV601348A  (mechanical)
FID1  Fiducial  [Fiducial10-20]  (value not drawn)
FID2  Fiducial  [Fiducial10-20]  (value not drawn)
FID3  Fiducial  [Fiducial10-20]  (value not drawn)
H1  NY PMS 440 0025 PH  [NY PMS 440 0025 PH]
H2  NY PMS 440 0025 PH  [NY PMS 440 0025 PH]
H3  NY PMS 440 0025 PH  [NY PMS 440 0025 PH]
H4  NY PMS 440 0025 PH  [NY PMS 440 0025 PH]
H5  1902C  [Keystone_1902C]
H6  1902C  [Keystone_1902C]
H7  1902C  [Keystone_1902C]
H8  1902C  [Keystone_1902C]
ZZ1  This Assembly Note is for PCB labels only  [AssemblyNoteLabel]  (no BOM)
ZZ2  These assemblies are ESD sensitive, ESD precautions shall be observed.  [AssemblyNote]  (no BOM)
ZZ3  These assemblies must be clean and free from flux and all contaminants. Use of no clean flux is not acceptable.  [AssemblyNote]  (no BOM)
ZZ4  These assemblies must comply with workmanship standards IPC-A-610 Class 2, unless otherwise specified.  [AssemblyNote]  (no BOM)

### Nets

Not connected (* = marked no-connect by the designer): H1 1; H2 1; H3 1; H4 1

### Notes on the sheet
- Variant
- Variant/Label Table
- Label Text
- 001

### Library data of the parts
!PCB? = PCB_OtherProject: Update Description to match PCB's description; Manufacturer: Any; SymbolCreator: a0412235; CompType: PCB; U/M: EA
FID1-FID3 = Fiducial: Fiducial mark.  There is nothing to buy or mount.; SymbolCreator: codlsc
H1-H4 = NY PMS 440 0025 PH: Machine Screw, Round, #4-40 x 1/4, Nylon, Philips panhead; Manufacturer: B&F Fastener Supply; CompType: Hardware; SymbolCreator: codlsc; U/M: EA
H5-H8 = 1902C: Standoff, Hex, 0.5"L #4-40 Nylon; Manufacturer: Keystone; CompType: Hardware
ZZ1 = AssemblyNoteLabel: SymbolCreator: a0412235
ZZ2-ZZ4 = AssemblyNote: SymbolCreator: codlsc

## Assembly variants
001: not fitted C23 C26 C35 C36 C37 C38 C39 FID1 FID2 FID3 L2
